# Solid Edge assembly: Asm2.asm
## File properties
Author: Sarvanan
Template: sync ansi assembly.asm
Last saved by: CADCIM
Revision: 15
Application: Solid Edge
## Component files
end plate.par
disk.par
support pin.par
spacer.par
center pin.par
bolt.par
nut.par
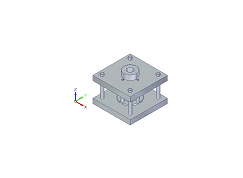
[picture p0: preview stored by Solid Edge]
